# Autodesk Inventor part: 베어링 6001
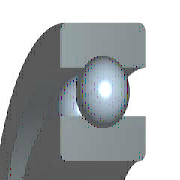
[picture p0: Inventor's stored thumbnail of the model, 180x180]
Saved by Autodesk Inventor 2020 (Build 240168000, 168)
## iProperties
Created: 2012-02
Part Number: 베어링 6001
Material: 알루미늄 6061
Description: 깊은 그루브 볼 베어링
Document SubType Name: Modeling
Standard: KS B 2023
Designer: mduedu
Standards Organization: KS
Language: ko-KR
Size Designation: 6001 - 12 x 28 x 8
Categories: <MemberInstance><Categories><Category DisplayName="샤프트 부품" InternalName="7f7aeb1f-a693-4053-b835-cee3144e0d98" Mnemonic="SHFT"><Category DisplayName="베어링" Inter
Density: 2.7 g/cm^3
Mass: 7.38048 g
Surface Area: 31.1809 cm^2
Volume: 2.73351 cm^3
Appearance: 노란색
IsCustomPart: 1
Author: mduedu
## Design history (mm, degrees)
sketch "스케치" dims "d0" = 4.16 (= -0.26 x WD + 0.26 x BD)
  geometry: L1 (1.92, 10)-(6.08, 10); L2 (4, 10)-(4, 7.92); L3 (4, 10)-(4, 12.08); L4 (2.454, 8.608)-(0, 8.608); L5 (0, 6)-(8, 6); L6 (2.454, 11.392)-(0, 11.392); L7 (0, 14)-(8, 14); L8 (8, 6)-(8, 8.608); L9 (5.546, 8.608)-(8, 8.608); L10 (5.546, 11.392)-(8, 11.392); L11 (8, 14)-(8, 11.392); L12 (-1.4, 0)-(8.4, 0) reference; L13 (0, -0.3)-(0, 5.3) reference
  constraints: 22 end point, 4 point on line, 2 collinear, 2 perpendicular, 2 symmetric about line, 1 midpoint, 1 parallel, 14 other
  dimensions: "d9" = 12 diameter of L5 L12 (= WD); "d11" = 28 diameter of L7 L12 (= BD); "d12" = 8 distance between parallel lines of L8 L13 (= KB); "d13" = 17.216 diameter of L9 L12 (= 0.326 x BD + 0.674 x WD)
revolve "본체" stored, may be unused: angle "d6" = 90 deg
revolve "볼" stored, may be unused: angle "d7" = 90 deg
pattern_circular "IDS_ARRAYBALL[SIMPL:T]" dims angle "d3" = 360 deg
body "Solid1"
fillet "모깎기1" dims "d1" = 0.3 (= KRS)
other parameters: "WD" = 12 [user parameter; used in 5 equation terms], "BD" = 28 [user parameter; used in 5 equation terms], "KB" = 8 [user parameter; used in 1 equation term], "KRS" = 0.3 [user parameter; used in 1 equation term], "d4" = 0, "d5" = 0, "d8" = 0, "d14" = 0, "d15" = 0, "BBA" = 0 [user parameter], "BC0" = 2360000 [user parameter], "BC" = 5070000 [user parameter], "BR" = 14 (= 0.5 x BD) [user parameter], "WR" = 6 (= 0.5 x WD) [user parameter]
